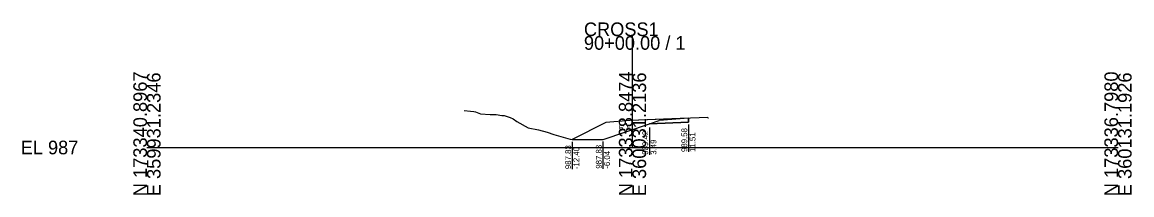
# Model space of a CAD drawing. Extents: x -26 to 1403, y -10 to 11027.
# Drawn here: x -25.7 to 202.8, y 4990.3 to 5025.7 of the extents above; entities that cross this region are included whole.
import ezdxf

# ---------------------------------------------------------------- set-up
doc = ezdxf.new("R2010")
doc.units = 0
for name, color, linetype in [('Default', 7, 'Continuous'), ('P_E_XS_Ground', 7, 'Continuous'), ('P_XS', 7, 'Continuous'), ('P_XS_EAR_CommonGrnd', 7, 'Continuous'), ('P_XS_Lane', 7, 'Continuous'), ('P_XS_Rock', 7, 'Continuous')]:
    doc.layers.add(name, color=color, linetype=linetype)

msp = doc.modelspace()

# ---------------------------------------------------------------- linework, layer by layer
at = {"layer": 'Default'}
for p, q in [((100, 5000), (100, 5022.86)), ((0, 5000), (100, 5000)), ((100, 5000), (200, 5000))]:
    msp.add_line(p, q, dxfattribs=at)
at = {"layer": 'P_E_XS_Ground'}
for p, q in [((65.34, 5007.62), (66.62, 5007.44)), ((66.62, 5007.44), (67.34, 5007.39)), ((67.34, 5007.39), (67.7, 5007.32)), ((67.7, 5007.32), (68.68, 5006.94)), ((68.68, 5006.94), (70.67, 5006.8)), ((70.67, 5006.8), (71.9, 5006.74)), ((71.9, 5006.74), (73.06, 5006.58)), ((73.06, 5006.58), (73.58, 5006.55)), ((73.58, 5006.55), (74.78, 5006.15)), ((74.78, 5006.15), (75.43, 5005.91)), ((75.43, 5005.91), (76.21, 5005.33)), ((76.21, 5005.33), (78.54, 5004.02)), ((94.5, 5005.12), (87.6, 5001.67)), ((99.5, 5005.52), (94.5, 5005.12)), ((115.51, 5006.16), (99.5, 5005.52)), ((115.51, 5006.06), (115.51, 5006.16)), ((115.51, 5006.06), (115.68, 5006.07)), ((78.54, 5004.02), (80.65, 5003.62)), ((80.65, 5003.62), (82.45, 5003.14)), ((82.45, 5003.14), (83.81, 5002.66)), ((83.81, 5002.66), (87.2, 5001.7)), ((87.2, 5001.7), (87.6, 5001.67))]:
    msp.add_line(p, q, dxfattribs=at)
at = {"layer": 'P_XS'}
for p in [(103.49, 5004.85), (111.51, 5006)]:
    msp.add_line(p, (105.51, 5005.52), dxfattribs=at)
at = {"layer": 'P_XS_EAR_CommonGrnd'}
msp.add_lwpolyline([(87.6, 5001.67), (93.96, 5001.67), (103.49, 5004.85), (111.51, 5005.17), (111.51, 5006), (99.5, 5005.52), (94.5, 5005.12)], close=True, dxfattribs=at)
at = {"layer": 'P_XS_Lane'}
for p, q in [((111.51, 5005.17), (103.49, 5004.85)), ((111.51, 5006), (111.51, 5005.17)), ((93.96, 5001.67), (103.49, 5004.85)), ((87.6, 5001.67), (93.96, 5001.67))]:
    msp.add_line(p, q, dxfattribs=at)
at = {"layer": 'P_XS_Rock'}
for p, q in [((103.48, 5004.13), (103.48, 4998.51)), ((111.52, 5004.69), (111.52, 4999.08)), ((87.59, 5001.15), (87.59, 4995.56)), ((93.91, 5001.25), (93.91, 4995.65))]:
    msp.add_line(p, q, dxfattribs=at)

# ---------------------------------------------------------------- texts
at = {"layer": 'Default'}
for s, p in [('CROSS1', (90, 5022.86)), ('90+00.00 / 1', (90, 5020.06)), ('EL 987', (-26, 4998.6))]:
    msp.add_text(s, height=2.8, dxfattribs=at).set_placement(p)
for s, p in [('N 173340.8967', (0, 4990)), ('E 359931.2346', (2.8, 4990)), ('N 173338.8474', (100, 4990)), ('E 360031.2136', (102.8, 4990)), ('N 173336.7980', (200, 4990)), ('E 360131.1926', (202.8, 4990))]:
    msp.add_text(s, height=2.8, rotation=90, dxfattribs=at).set_placement(p)
at = {"layer": 'P_XS_Rock'}
for s, rotation, p in [('6:1', 18.4349, (97.4, 5003.31)), ('989.42', 90, (103.23, 4998.51)), ('989.58', 90, (111.27, 4999.08)), ('11.51', 90, (112.97, 4999.08)), ('987.83', 90, (87.34, 4995.56)), ('987.83', 90, (93.66, 4995.65)), ('3.49', 90, (104.93, 4998.51)), ('-12.40', 90, (89.04, 4995.56)), ('-6.04', 90, (95.36, 4995.65))]:
    msp.add_text(s, height=1.2, rotation=rotation, dxfattribs=at).set_placement(p)

doc.saveas('drawing.dxf')
